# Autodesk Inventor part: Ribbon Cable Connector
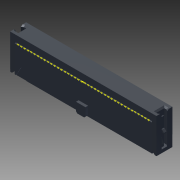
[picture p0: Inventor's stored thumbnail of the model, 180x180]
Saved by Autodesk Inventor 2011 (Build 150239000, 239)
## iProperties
Company: Autodesk Inc.
Created: 2006-07
Part Number: Ribbon Cable Connector
Document SubType Name: Modeling
Designer: Autodesk Inc.
Categories: <MemberInstance><Categories><Category DisplayName="" Mnemonic="CABLEANDHARNESS" InternalName="e4a7e005-5e42-4d16-b293-125e7f0d0512"><Category DisplayName="" Mne
Density: 1 g/cm^3
Mass: 4.05178 g
Surface Area: 35.294 cm^2
Volume: 4.05178 cm^3
Title: Personal Computer
Author: Autodesk Inc.
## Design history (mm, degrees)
sketch "Sketch1"
  geometry: L1 (26.03, -3)-(-26.03, -3); L2 (-25.28, -1.5)-(-25.28, -2.1); L3 (-26.03, -3)-(-26.03, -2.1); L4 (-25.28, -2.1)-(-26.03, -2.1); L5 (-26.03, -1.5)-(-25.28, -1.5); L6 (-26.03, -1.5)-(-26.03, 3); L7 (25.28, 1.5)-(25.28, 2.1); L8 (26.03, 1.5)-(26.03, -3); L9 (26.03, 1.5)-(25.28, 1.5); L10 (25.28, 2.1)-(26.03, 2.1); L11 (26.03, 3)-(26.03, 2.1); L12 (0, 3)-(0, -3); L13 (-26.03, 3)-(26.03, 3); 2 further points
  constraints: 26 end point, 8 parallel, 3 midpoint, 3 perpendicular, 2 horizontal, 1 coincident
  dimensions: "d0" = 52.06 distance of L1.start L1.end (derived); "d1" = 6 distance of L1.end L6.end; "d4" = 0.9 distance between parallel lines of L1 L4; "d5" = 0.75 distance of L2.end L3.end; "d6" = 0.6 distance of L2.start L2.end; "d8" = 0.75 distance of L7.end L10.end; "d9" = 0.6 distance of L7.start L7.end; "d10" = 6 distance of L1.start L11.start; "d12" = 0.9 distance of L11.start L10.end
extrude "Extrusion1" new body sketch "Sketch1" distance "d13" = 10.2; taper "d14" = 0 deg
sketch "Sketch2"
  geometry: L1 (0, 0)-(52.06, 0) reference; L2 (24.23, 3.6)-(27.83, 3.6); L3 (27.83, 3.6)-(27.83, 0.5); L4 (27.33, 0)-(24.73, 0); L5 (24.23, 0.5)-(24.23, 3.6); L6 (24.23, 0.5)-(24.73, 0); L7 (27.83, 0.5)-(27.33, 0); 1 further point
  constraints: 12 end point, 2 midpoint, 2 parallel, 1 horizontal, 1 perpendicular
  dimensions: "d15" = 3.6 distance of L2.start L2.end; "d17" = 0.5 horizontal distance of L4.end L5.start; "d19" = 135 deg angle of L6 L5; "d20" = 135 deg angle of L7 L3; "d21" = 0.5 horizontal distance of L4.start L3.end; "d22" = 3.6 distance between parallel lines of L1 L2
extrude "Extrusion2" join sketch "Sketch2" distance "d23" = 1; taper "d24" = 0 deg
sketch "Sketch3"
  geometry: L1 (-26.03, 3.6)-(-26.28, 3.6); L2 (-27.03, 2.1)-(-27.03, 1.22); L3 (-27.03, 1.22)-(-26.03, 1.22); L4 (-26.03, 1.22)-(-26.03, 3.6); L5 (26.03, 10.2)-(-26.03, 10.2) reference; L6 (0, 10.2)-(0, 0); L7 (-26.03, 0)-(26.03, 0) reference; L8 (-26.28, 3.6)-(-27.03, 2.1); L9 (26.03, 3.6)-(26.28, 3.6); L10 (27.03, 2.1)-(27.03, 1.22); L11 (27.03, 1.22)-(26.03, 1.22); L12 (26.03, 1.22)-(26.03, 3.6); L13 (26.28, 3.6)-(27.03, 2.1)
  constraints: 22 end point, 5 symmetric about line, 2 midpoint, 2 parallel, 2 perpendicular, 1 horizontal
  dimensions: "d25" = 52.06 diameter of L4 L6 (derived); "d26" = 1.22 distance between parallel lines of L3 L7; "d28" = 1 distance of L2.end L3.end; "d29" = 1.5 vertical distance of L1.end L2.start; "d30" = 0.88 distance of L2.start L2.end; "d31" = 0.25 distance of L1.start L1.end
extrude "Extrusion3" join sketch "Sketch3" stored distance "d32" = 1; taper "d33" = 0 deg
sketch "Sketch4"
  geometry: L1 (26.03, 3.6)-(26.28, 3.6) reference; L2 (26.03, 6.263)-(26.28, 6.263); L3 (27.03, 5.513)-(27.03, 5.263); L4 (27.03, 5.263)-(26.03, 5.263); L5 (26.03, 5.263)-(26.03, 6.263); L6 (-26.03, 10.2)-(26.03, 10.2) reference; L7 (26.03, 0)-(-26.03, 0) reference; L8 (0, 10.2)-(0, 0); L9 (26.28, 6.263)-(27.03, 5.513); L10 (-26.03, 5.263)-(-26.03, 6.263); L11 (-26.03, 6.263)-(-26.28, 6.263); L12 (-26.28, 6.263)-(-27.03, 5.513); L13 (-27.03, 5.513)-(-27.03, 5.263); L14 (-27.03, 5.263)-(-26.03, 5.263)
  constraints: 22 end point, 5 symmetric about line, 2 midpoint, 2 parallel, 1 horizontal, 1 perpendicular
  dimensions: "d34" = 1.663 distance between parallel lines of L4 L1; "d35" = 52.06 diameter of L5 L8 (derived); "d36" = 1 distance of L3.end L4.end; "d38" = 0.25 distance of L2.start L2.end; "d39" = 1 distance of L4.end L2.start; "d40" = 0.25 distance of L3.start L3.end
extrude "Extrusion4" join sketch "Sketch4" distance "d41" = 1; taper "d42" = 0 deg
sketch "Sketch5"
  geometry: L1 (26.28, -3.6)-(26.03, -3.6) reference; L2 (26.28, -6.263)-(26.03, -6.263); L3 (26.03, -6.263)-(26.03, -5.263); L4 (26.03, -5.263)-(27.03, -5.263); L5 (27.03, -5.263)-(27.03, -5.513); L6 (26.03, -10.2)-(-26.03, -10.2) reference; L7 (1.3, 0)-(-1.3, 0) reference; L8 (0, 0)-(0, -10.2); L9 (26.28, -6.263)-(27.03, -5.513); L10 (-26.03, -6.263)-(-26.03, -5.263); L11 (-26.28, -6.263)-(-26.03, -6.263); L12 (-26.28, -6.263)-(-27.03, -5.513); L13 (-27.03, -5.263)-(-27.03, -5.513); L14 (-26.03, -5.263)-(-27.03, -5.263)
  constraints: 22 end point, 5 symmetric about line, 2 midpoint, 2 parallel, 1 horizontal, 1 perpendicular
  dimensions: "d43" = 1.663 distance between parallel lines of L1 L4; "d44" = 52.06 diameter of L3 L8 (derived); "d45" = 1 distance of L2.end L3.end; "d46" = 1 distance of L3.end L4.end; "d47" = 0.25 distance of L2.start L2.end; "d48" = 0.25 distance of L4.end L5.end
extrude "Extrusion5" join sketch "Sketch5" distance "d49" = 1; taper "d50" = 0 deg
sketch "Sketch6"
  geometry: L1 (0, -10.2)-(24.73, -10.2) reference; L2 (-36.97, -6.736)-(-34.97, -10.2); L3 (-38.97, -10.2)-(-36.97, -6.736); L4 (-38.97, -10.2)-(-34.97, -10.2); L5 (0.5, -10.2)-(2.5, -6.736); L6 (2.5, -6.736)-(4.5, -10.2); L7 (0.5, -10.2)-(4.5, -10.2)
  constraints: 12 end point, 4 equal length, 2 point on line, 1 collinear
  dimensions: "d61" = 0.5 distance of L5.start L1.start; "d62" = 4 distance of L5.start L6.end
extrude "Extrusion6" cut sketch "Sketch6" distance "d63" = 0.1; taper "d64" = 0 deg
sketch "Sketch7"
  geometry: L1 (26.03, 3)-(26.03, -1.5) reference; L2 (23.755, 1.645)-(24.505, 1.645); L3 (24.505, 1.645)-(24.505, 0.895); L4 (24.505, 0.895)-(23.755, 0.895); L5 (23.755, 0.895)-(23.755, 1.645); L6 (23.755, -0.895)-(24.505, -0.895); L7 (24.505, -0.895)-(24.505, -1.645); L8 (24.505, -1.645)-(23.755, -1.645); L9 (23.755, -1.645)-(23.755, -0.895); L10 (24.13, 0.895)-(24.13, -0.895); 2 further points
  constraints: 18 end point, 7 equal length, 4 parallel, 3 midpoint, 3 perpendicular, 2 horizontal, 1 horizontal alignment
  dimensions: "d65" = 0.75 distance of L2.start L2.end; "d66" = 2.54 distance between parallel lines of L6 L2; "d67" = 1.525 distance between parallel lines of L1 L7
extrude "Extrusion7" cut sketch "Sketch7" distance "d68" = 3; taper "d69" = 0 deg
chamfer "Chamfer1" distance "d70" = 0.5; stored, may be unused: second distance "d71" = 2, angle "d72" = 45 deg
workplane "Work Plane1"
sketch "Sketch8"
  geometry: L1 (-27.011, -1.499)-(-26.16, -1.499); L2 (-27.715, -1.03)-(-27.011, -1.499); L3 (-27.715, -3.03)-(-27.715, -1.03); L4 (27.715, -3.03)-(-27.715, -3.03); L5 (-27.715, 3.03)-(27.715, 3.03); L6 (-26.16, -1.499)-(-26.16, 1.499); L7 (-26.03, 3)-(26.03, 3) reference; L8 (-26.03, -1.5)-(-26.03, 3) reference; L9 (-25.28, -1.5)-(-26.03, -1.5) reference; L10 (-25.28, -2.1)-(-25.28, -1.5) reference; L11 (-26.03, -2.1)-(-25.28, -2.1) reference; L12 (-26.03, -3)-(-26.03, -2.1) reference; L13 (26.03, -3)-(-26.03, -3) reference; L14 (26.03, 1.5)-(26.03, -3) reference; L15 (25.28, 1.5)-(26.03, 1.5) reference; L16 (25.28, 2.1)-(25.28, 1.5) reference; L17 (26.03, 2.1)-(25.28, 2.1) reference; L18 (26.03, 3)-(26.03, 2.1) reference; L19 (0, 3)-(0, -3); L20 (-26.16, 0)-(-42.954, 0); L21 (-27.715, 1.03)-(-27.011, 1.499); L22 (-27.715, 3.03)-(-27.715, 1.03); L23 (-27.011, 1.499)-(-26.16, 1.499); L24 (27.715, 3.03)-(27.715, 1.03); L25 (27.715, 1.03)-(27.011, 1.499); L26 (27.011, 1.499)-(26.16, 1.499); L27 (26.16, -1.499)-(26.16, 1.499); L28 (27.011, -1.499)-(26.16, -1.499); L29 (27.715, -1.03)-(27.011, -1.499); L30 (27.715, -3.03)-(27.715, -1.03); 4 further points
  constraints: 36 end point, 8 symmetric about line, 5 midpoint, 4 perpendicular, 3 parallel, 1 coincident, 1 horizontal, 1 horizontal alignment
  dimensions: "d160" = 2 distance of L3.start L2.start; "d161" = 0.85079 distance of L1.start L1.end; "d162" = 2.99894 distance of L1.end L6.end; "d163" = 56.3099 deg angle of L3 L2; "d164" = 0.13 distance between parallel lines of L8 L6; "d165" = 55.43 distance of L5.start L5.end (derived)
extrude "Extrusion8" join sketch "Sketch8" distance "d90" = 2.5; taper "d91" = 0 deg
sketch "Sketch10"
  geometry: L1 (-27.715, 3.03)-(-27.715, 1.03) reference; L2 (27.715, 3.03)-(-27.715, 3.03) reference; L3 (27.715, 1.03)-(27.715, 3.03) reference; L4 (27.011, 1.499)-(27.715, 1.03) reference; L5 (26.16, 1.499)-(27.011, 1.499) reference; L6 (26.16, -1.499)-(26.16, 1.499) reference; L7 (27.011, -1.499)-(26.16, -1.499) reference; L8 (27.715, -1.03)-(27.011, -1.499) reference; L9 (27.715, -3.03)-(27.715, -1.03) reference; L10 (-27.715, -3.03)-(27.715, -3.03) reference; L11 (-27.715, -1.03)-(-27.715, -3.03) reference; L12 (-27.011, -1.499)-(-27.715, -1.03) reference; L13 (-26.16, -1.499)-(-27.011, -1.499) reference; L14 (-26.16, 1.499)-(-26.16, -1.499) reference; L15 (-27.011, 1.499)-(-26.16, 1.499) reference; L16 (-27.715, 1.03)-(-27.011, 1.499) reference; L17 (26.03, -1.5)-(25.28, -1.5) reference; L18 (25.28, -1.5)-(25.28, -2.1) reference; L19 (25.28, -2.1)-(26.03, -2.1) reference; L20 (-26.03, 1.5)-(-25.28, 1.5) reference; L21 (-25.28, 1.5)-(-25.28, 2.1) reference; L22 (-25.28, 2.1)-(-26.03, 2.1) reference; L23 (-26.04, 1.51)-(-25.29, 1.51); L24 (-25.29, 1.51)-(-25.29, 2.09); L25 (-25.29, 2.09)-(-26.04, 2.09); L26 (-26.04, 2.09)-(-26.04, 3.03); L27 (26.04, -2.09)-(25.29, -2.09); L28 (25.29, -2.09)-(25.29, -1.51); L29 (25.29, -1.51)-(26.04, -1.51); L30 (26.04, -3.03)-(26.04, -2.09); L31 (-26.16, -1.499)-(-26.04, -1.499); L32 (-26.16, 1.499)-(-26.04, 1.499); L33 (-26.04, -3.03)-(-26.04, -1.499); L34 (-26.04, 1.499)-(-26.04, 1.51); L35 (26.16, 1.499)-(26.04, 1.499); L36 (26.16, -1.499)-(26.04, -1.499); L37 (26.04, -1.51)-(26.04, -1.499); L38 (26.04, 1.499)-(26.04, 3.03); 4 further points
  constraints: 32 end point, 8 perpendicular, 7 parallel, 4 midpoint, 4 point on line, 2 horizontal, 2 horizontal alignment
  dimensions: "d167" = 0.01 distance between parallel lines of L20 L23; "d168" = 0.01 distance between parallel lines of L21 L24; "d170" = 0.01 distance from line of L26 L22.end; "d172" = 0.01 distance between parallel lines of L19 L27; "d173" = 0.01 distance between parallel lines of L18 L28; "d174" = 0.01 distance from line of L30 L19.end; "d180" = 0.01 distance from line of L20.start L34; "d181" = 0.12 distance of L13.start L31.end; "d182" = 0.01 distance of L36.end L17.start; "d183" = 0.12 distance of L5.start L35.end
extrude "Extrusion9" join sketch "Sketch10" distance "d157" = 10.7; taper "d158" = 0 deg
sketch "Sketch12"
  geometry: L1 (27.715, 13.2)-(-27.715, 13.2) reference; L2 (0, 13.2)-(0, 4.865); L3 (-27.715, 13.2)-(-27.715, 0) reference; L4 (-27.715, 0)-(-26.04, 0); L5 (-26.04, 0)-(-26.04, 1.21); L6 (-26.04, 1.21)-(-27.715, 1.21); L7 (-27.715, 1.21)-(-27.715, 0); L8 (-26.28, 3.6)-(-26.03, 3.6) reference; L9 (-27.03, 2.1)-(-26.28, 3.6) reference; L10 (-27.03, 1.22)-(-27.03, 2.1) reference; L11 (-26.03, 1.22)-(-27.03, 1.22) reference; L12 (26.04, 0)-(26.04, 1.21); L13 (26.04, 1.21)-(27.715, 1.21); L14 (27.715, 1.21)-(27.715, 0); L15 (27.715, 0)-(26.04, 0); L16 (-26.03, 3.6)-(-26.03, 1.22) reference
  constraints: 18 end point, 4 symmetric about line, 2 parallel, 2 perpendicular, 1 horizontal, 1 midpoint
  dimensions: "d177" = 0.01 distance between parallel lines of L11 L6; "d243" = 1.675 distance of L3.end L4.end
extrude "Extrusion10" join sketch "Sketch12" stored distance "d178" = 6.06; taper "d179" = 0 deg
chamfer "Chamfer2" distance "d185" = 1; stored, may be unused: second distance "d186" = 2, angle "d187" = 45 deg
chamfer "Chamfer3" distance "d188" = 1.749; stored, may be unused: second distance "d189" = 2, angle "d190" = 45 deg
chamfer "Chamfer4" distance "d191" = 10.71; stored, may be unused: second distance "d192" = 0.03, angle "d193" = 45 deg
chamfer "Chamfer5" distance "d194" = 10.71; stored, may be unused: second distance "d195" = 0.03, angle "d196" = 45 deg
chamfer "Chamfer8" distance "d203" = 0.5; stored, may be unused: second distance "d204" = 0.03, angle "d205" = 45 deg
sketch "Sketch20"
  geometry: 1 further point
node "1"
node "2"
node "3"
node "4"
node "5"
node "6"
node "7"
node "8"
node "9"
node "10"
node "11"
node "12"
node "13"
node "14"
node "15"
node "16"
node "17"
node "18"
node "19"
node "20"
node "21"
node "22"
node "23"
node "24"
node "25"
node "26"
node "27"
node "28"
node "29"
node "30"
node "31"
node "32"
node "33"
node "34"
node "35"
node "36"
node "37"
node "38"
node "39"
node "40"
sketch "Sketch22"
  geometry: L1 (55.43, -2.49)-(0, -2.49) reference; L2 (55.43, 0)-(55.43, -2.49) reference; L3 (55.43, 0)-(0, 0) reference; L4 (0, 0)-(0, -2.49) reference; L5 (2.95, -2.75)-(52.48, -2.75); 1 further point
  constraints: 2 end point, 1 midpoint, 1 perpendicular
workpoint "Work Point173"
sketch "Sketch23"
  geometry: L1 (0, 2.49)-(55.43, 2.49) reference; L2 (0, 2.49)-(0, 0) reference; L3 (0, 0)-(55.43, 0) reference; L4 (55.43, 0)-(55.43, 2.49) reference; 1 further point
workpoint "Work Point174"
body "Solid1"
pattern_linear "Rectangular Pattern1" dims "d75" = 2.54
node "Projected Loop2"
node "Projected Loop3"
node "Projected Loop4"
other parameters: "DimA" = 52.06 [user parameter], "DimB" = 55.43 [user parameter], "DimC" = 24.765 [user parameter], "d123" = 0.01, "d126" = 0.01, "d148" = 0.01, "d152" = 0.01, "d166" = 0.01, "d169" = 0.01, "d171" = 0.01, "d175" = 0.01, "d234" = 10.7
